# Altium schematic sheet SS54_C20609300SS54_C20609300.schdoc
size 127 x 101 mm
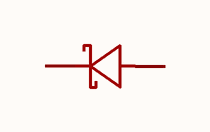
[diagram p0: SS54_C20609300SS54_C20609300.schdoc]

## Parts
U?  ss54_c20609300  [SMA_L4.3-W2.6-LS5.1-RD]  (value not drawn)

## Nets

Not connected (* = marked no-connect by the designer): U? 1(K) 2(A)

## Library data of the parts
U? = ss54_c20609300: 二极管配置:1个独立式;正向压降(Vf):550mV@5A;直流反向耐压(Vr):40V;整流电流:5A;; Manufacturer: JSMSEMI(杰盛微); ManufacturerPart: SS54; AddInBom: yes; ModelId: 1d20a911e9694ba6aaf6e9207164e4da; ModelTransform: 196.4563,102.362,0,0,0,0,0.001,-0.001,0; Diode Configuration: 1个独立式; Voltage - DC Reverse(Vr): 40V; Current - Rectified: 5A; Reverse Leakage Current (Ir): 100uA@40V; Operating Junction Temperature Range: -55℃~+150℃; Non-Repetitive Peak Forward Surge Current: 100A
